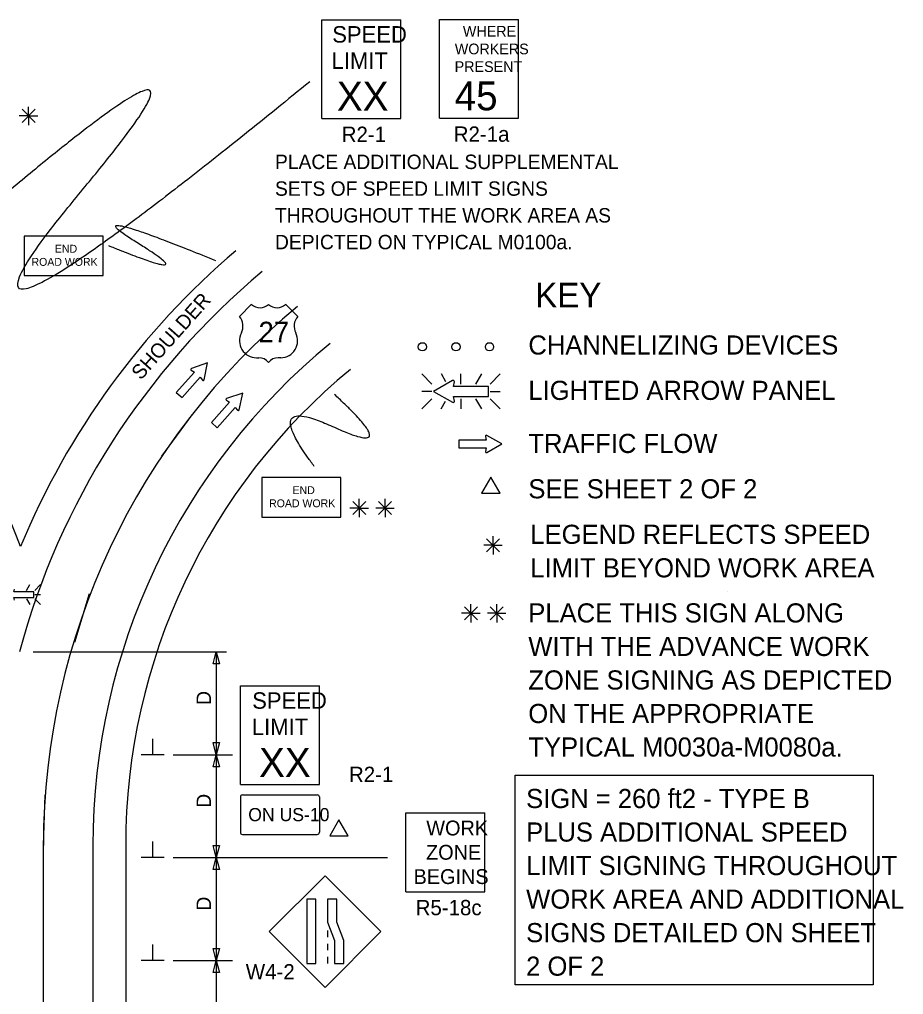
# Model space of a CAD drawing. Extents: x 16303 to 18475, y 5704 to 6974.
# Drawn here: x 17006 to 17435.6, y 6452.8 to 6926.7 of the extents above; entities that cross this region are included whole.
import ezdxf

# ---------------------------------------------------------------- set-up
doc = ezdxf.new("R2010")
doc.units = 0
for name, color, linetype in [('ALI_LEGAL_EX', 7, 'Continuous'), ('MT_SCRATCH_LEVEL_E', 7, 'Continuous'), ('PAVT_EDGE_EX', 7, 'Continuous'), ('TRAFFIC_SIGNS_PR', 7, 'Continuous'), ('TYPICAL_EX', 7, 'Continuous'), ('TYPICAL_TEXT_DIMEN_EX', 7, 'Continuous'), ('TYPICAL_TEXT_DIMEN_PR', 7, 'Continuous')]:
    doc.layers.add(name, color=color, linetype=linetype)

msp = doc.modelspace()

# ---------------------------------------------------------------- linework, layer by layer
at = {"layer": 'ALI_LEGAL_EX'}
for p, q in [((17039.84, 6647.53), (17032.85, 6623.88)), ((17017.65, 6024.8), (17017.65, 6525.15))]:
    msp.add_line(p, q, dxfattribs=at)
for points in [[(17075.14, 6714.42), (17089.89, 6734.61)], [(17017.7, 6524.8), (17017.65, 6525.15), (17018.48, 6549.78)]]:
    msp.add_lwpolyline(points, dxfattribs=at)
msp.add_arc((17357.65, 6525.15), 340, 129.5666, 180, dxfattribs=at)
at = {"layer": 'MT_SCRATCH_LEVEL_E'}
for p, q in [((17097.48, 6759.79), (17089.6, 6757.11)), ((17095.77, 6751.62), (17097.48, 6759.79)), ((17091.04, 6755.33), (17082.24, 6745.42)), ((17089.5, 6756.28), (17091.04, 6755.33)), ((17085.03, 6742.93), (17093.84, 6752.84)), ((17093.84, 6752.84), (17094.96, 6751.43)), ((17082.24, 6745.42), (17085.03, 6742.93)), ((17114.56, 6745.13), (17106.68, 6742.45)), ((17112.85, 6736.96), (17114.56, 6745.13)), ((17108.12, 6740.67), (17099.32, 6730.76)), ((17106.59, 6741.62), (17108.12, 6740.67)), ((17102.12, 6728.28), (17110.92, 6738.19)), ((17110.92, 6738.19), (17112.04, 6736.77)), ((17099.32, 6730.76), (17102.12, 6728.28)), ((17232.83, 6722.29), (17219.58, 6722.29)), ((17219.58, 6722.29), (17219.58, 6718.55)), ((17232.52, 6724.07), (17232.83, 6722.29)), ((17240.44, 6720.44), (17233.2, 6724.55)), ((17219.58, 6718.55), (17232.83, 6718.55)), ((17232.83, 6718.55), (17232.52, 6716.77)), ((17233.2, 6716.29), (17240.44, 6720.44))]:
    msp.add_line(p, q, dxfattribs=at)
for centre, start, end in [((17089.75, 6756.67), 108.8028, 238.3418), ((17095.31, 6751.73), 218.4141, 348.1511), ((17106.84, 6742.01), 108.8028, 238.3418), ((17112.4, 6737.07), 218.4141, 348.1511), ((17232.98, 6724.14), 60.4248, 189.9638), ((17232.98, 6716.7), 170.0362, 299.7731)]:
    msp.add_arc(centre, 0.463, start, end, dxfattribs=at)
at = {"layer": 'PAVT_EDGE_EX'}
for p, q in [((17041.65, 6525.15), (17041.65, 6062.71)), ((17057.65, 6525.15), (17057.65, 6062.71))]:
    msp.add_line(p, q, dxfattribs=at)
for centre, radius, start, end in [((16629.65, 6525.15), 404, 21.0961, 68.7791), ((17357.65, 6525.15), 380, 130.4392, 157.5011), ((17357.65, 6525.15), 364, 129.9322, 165.0045), ((17357.65, 6525.15), 316, 129.4107, 180), ((17357.65, 6525.15), 300, 129.4882, 180), ((17357.65, 6525.15), 300, 180, 180.00000277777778), ((17357.65, 6475.15), 300, 180, 180.00000277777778)]:
    msp.add_arc(centre, radius, start, end, dxfattribs=at)
at = {"layer": 'TRAFFIC_SIGNS_PR'}
for p, q in [((17153.01, 6926.66), (17191.41, 6926.66)), ((17153.01, 6878.66), (17153.01, 6926.66)), ((17191.41, 6878.66), (17191.41, 6926.66)), ((17210.2, 6926.75), (17248.6, 6926.75)), ((17210.2, 6878.75), (17210.2, 6926.75)), ((17248.6, 6878.75), (17248.6, 6926.75)), ((17153.01, 6878.66), (17191.41, 6878.66)), ((17210.2, 6878.75), (17248.6, 6878.75)), ((17201.51, 6754.45), (17206.44, 6749.51)), ((17213.27, 6750.63), (17211.06, 6754.45)), ((17220.59, 6749.51), (17220.59, 6754.45)), ((17227.83, 6749.51), (17230.68, 6754.45)), ((17234.74, 6749.51), (17239.68, 6754.45)), ((17206.44, 6745.96), (17201.51, 6745.96)), ((17234.74, 6745.96), (17239.68, 6745.96)), ((17201.51, 6737.47), (17206.44, 6742.4)), ((17211.02, 6737.47), (17213.13, 6741.13)), ((17220.59, 6742.4), (17220.59, 6737.47)), ((17230.72, 6737.47), (17227.87, 6742.4)), ((17234.74, 6742.4), (17239.68, 6737.47)), ((17009.51, 6649.19), (17011.14, 6652.01)), ((17013.47, 6649.19), (17016.29, 6652.02)), ((17013.47, 6647.16), (17016.29, 6647.16)), ((17011.17, 6642.31), (17009.54, 6645.13)), ((17013.47, 6645.13), (17016.29, 6642.31)), ((17113.37, 6602.81), (17151.77, 6602.81)), ((17113.37, 6554.81), (17113.37, 6602.81)), ((17151.77, 6554.81), (17151.77, 6602.81)), ((17113.37, 6554.81), (17151.77, 6554.81)), ((17113.37, 6548.81), (17113.37, 6531.61)), ((17114.37, 6549.81), (17150.77, 6549.81)), ((17151.77, 6548.81), (17151.77, 6531.61)), ((17193.74, 6502.73), (17193.74, 6541.13)), ((17193.74, 6541.13), (17232.14, 6541.13)), ((17232.14, 6502.73), (17232.14, 6541.13)), ((17114.37, 6530.61), (17150.77, 6530.61)), ((17154.51, 6510.52), (17127.36, 6483.37)), ((17181.66, 6483.37), (17154.51, 6510.52)), ((17193.74, 6502.73), (17232.14, 6502.73)), ((17127.36, 6483.37), (17154.51, 6456.21)), ((17154.51, 6456.21), (17181.66, 6483.37)), ((17155.75, 6483.86), (17155.75, 6480.66)), ((17155.75, 6477.46), (17155.75, 6474.26)), ((17155.75, 6471.06), (17155.75, 6467.86))]:
    msp.add_line(p, q, dxfattribs=at)
for points in [[(17008.25, 6802.25), (17046.65, 6802.25), (17046.65, 6821.45), (17008.25, 6821.45)], [(17123.73, 6684.89), (17162.13, 6684.89), (17162.13, 6704.09), (17123.73, 6704.09)], [(17145.61, 6499.1), (17145.61, 6467.86), (17150.11, 6467.86), (17150.11, 6499.1)], [(17155.75, 6499.1), (17155.75, 6487.92), (17159.09, 6479.04), (17159.09, 6467.86), (17163.59, 6467.86), (17163.59, 6479.04), (17160.24, 6487.92), (17160.24, 6499.1)]]:
    msp.add_lwpolyline(points, close=True, dxfattribs=at)
for points in [[(17216.52, 6751.23), (17207.23, 6745.96), (17216.52, 6740.64)], [(17217.39, 6741.27), (17216.99, 6743.53), (17234.01, 6743.53), (17234.01, 6748.34), (17216.99, 6748.34), (17217.4, 6750.62)], [(17003.55, 6644.48), (17003.32, 6645.78), (17013.05, 6645.78), (17013.05, 6648.52), (17003.32, 6648.52), (17003.56, 6649.82)]]:
    msp.add_lwpolyline(points, dxfattribs=at)
for centre in [(17201.85, 6767.64), (17218.15, 6767.64), (17234.45, 6767.64)]:
    msp.add_circle(centre, 2, dxfattribs=at)
for centre, radius, start, end in [((17216.81, 6750.71), 0.598, 350.7308, 118.8916), ((17216.81, 6741.16), 0.597, 241.4833, 9.9593), ((17114.37, 6548.81), 1, 90, 180), ((17150.77, 6548.81), 1, 0, 90), ((17114.37, 6531.61), 1, 180, 270), ((17150.77, 6531.61), 1, 270, 0)]:
    msp.add_arc(centre, radius, start, end, dxfattribs=at)
at = {"layer": 'TYPICAL_EX'}
for p, q in [((17112.93, 6782.38), (17118.83, 6788.28)), ((17141.23, 6782.38), (17135.33, 6788.28)), ((17121.17, 6762.32), (17122.35, 6762.32)), ((17132.98, 6762.32), (17131.8, 6762.32))]:
    msp.add_line(p, q, dxfattribs=at)
for centre, radius, start, end in [((17122.95, 6792.57), 5.96, 226.1404, 313.8596), ((17131.21, 6792.57), 5.96, 226.1404, 313.8596), ((17107.34, 6777.66), 7.31, 333.0977, 40.1936), ((17146.82, 6777.66), 7.31, 139.8064, 206.9023), ((17121.19, 6770.57), 8.24, 152.6698, 269.9013), ((17132.97, 6770.57), 8.24, 270.0987, 27.3302), ((17122.37, 6756.42), 5.91, 37.1038, 90.1385), ((17131.79, 6756.42), 5.91, 89.8615, 142.8962)]:
    msp.add_arc(centre, radius, start, end, dxfattribs=at)
at = {"layer": 'TYPICAL_TEXT_DIMEN_EX'}
msp.add_lwpolyline([(17246.97, 6559.43), (17420.83, 6559.43), (17420.83, 6457.5), (17246.97, 6457.5)], close=True, dxfattribs=at)
at = {"layer": 'TYPICAL_TEXT_DIMEN_PR'}
for p, q in [((17007.28, 6883.1), (17013.65, 6876.73)), ((17013.65, 6883.1), (17007.28, 6876.73)), ((17010.46, 6879.91), (17010.46, 6884.37)), ((17010.46, 6879.91), (17005.93, 6879.91)), ((17010.46, 6879.91), (17013.65, 6879.91)), ((17010.46, 6879.91), (17014.94, 6879.91)), ((17010.46, 6879.91), (17010.46, 6875.41)), ((17171.16, 6689.26), (17171.16, 6693.72)), ((17183.71, 6689.26), (17183.71, 6693.72)), ((17171.16, 6689.26), (17166.62, 6689.26)), ((17167.97, 6692.45), (17174.34, 6686.07)), ((17174.34, 6692.45), (17167.97, 6686.07)), ((17171.16, 6689.26), (17174.34, 6689.26)), ((17171.16, 6689.26), (17175.63, 6689.26)), ((17171.16, 6689.26), (17171.16, 6684.76)), ((17183.71, 6689.26), (17179.18, 6689.26)), ((17186.9, 6692.45), (17180.52, 6686.07)), ((17180.53, 6692.45), (17186.9, 6686.07)), ((17183.71, 6689.26), (17186.9, 6689.26)), ((17183.71, 6689.26), (17188.19, 6689.26)), ((17183.71, 6689.26), (17183.71, 6684.76)), ((17233.01, 6674.32), (17239.39, 6667.95)), ((17239.39, 6674.32), (17233.01, 6667.95)), ((17236.2, 6671.13), (17236.2, 6675.59)), ((17236.2, 6671.13), (17231.67, 6671.13)), ((17236.2, 6671.13), (17239.39, 6671.13)), ((17236.2, 6671.13), (17240.68, 6671.13)), ((17236.2, 6671.13), (17236.2, 6666.63)), ((17222.24, 6641.27), (17228.61, 6634.9)), ((17228.61, 6641.27), (17222.24, 6634.9)), ((17225.42, 6638.08), (17225.42, 6642.54)), ((17234.79, 6641.27), (17241.17, 6634.9)), ((17241.17, 6641.27), (17234.79, 6634.9)), ((17237.98, 6638.08), (17237.98, 6642.54)), ((17225.42, 6638.08), (17220.89, 6638.08)), ((17225.42, 6638.08), (17228.61, 6638.08)), ((17225.42, 6638.08), (17229.9, 6638.08)), ((17225.42, 6638.08), (17225.42, 6633.58)), ((17237.98, 6638.08), (17233.45, 6638.08)), ((17237.98, 6638.08), (17241.17, 6638.08)), ((17237.98, 6638.08), (17242.46, 6638.08)), ((17237.98, 6638.08), (17237.98, 6633.58)), ((17012.72, 6619.33), (17106.65, 6619.33)), ((17100.08, 6613.47), (17101.65, 6619.33)), ((17101.65, 6619.33), (17101.65, 6569.33)), ((17101.65, 6619.33), (17103.22, 6613.47)), ((17101.65, 6613.47), (17100.08, 6613.47)), ((17103.22, 6613.47), (17101.65, 6613.47)), ((17070.77, 6569.33), (17070.77, 6577.11)), ((17101.65, 6569.33), (17100.08, 6575.19)), ((17100.08, 6575.19), (17101.65, 6575.19)), ((17101.65, 6575.19), (17103.22, 6575.19)), ((17103.22, 6575.19), (17101.65, 6569.33)), ((17076.4, 6569.33), (17065.15, 6569.33)), ((17080.65, 6569.33), (17109.57, 6569.33)), ((17100.08, 6563.47), (17101.65, 6569.33)), ((17101.65, 6569.33), (17101.65, 6519.33)), ((17101.65, 6569.33), (17103.22, 6563.47)), ((17101.65, 6563.47), (17100.08, 6563.47)), ((17103.22, 6563.47), (17101.65, 6563.47)), ((17070.77, 6519.33), (17070.77, 6527.11)), ((17101.65, 6519.33), (17100.08, 6525.19)), ((17100.08, 6525.19), (17101.65, 6525.19)), ((17101.65, 6525.19), (17103.22, 6525.19)), ((17103.22, 6525.19), (17101.65, 6519.33)), ((17076.4, 6519.33), (17065.15, 6519.33)), ((17080.65, 6519.33), (17184.86, 6519.33)), ((17100.08, 6513.47), (17101.65, 6519.33)), ((17101.65, 6519.33), (17103.22, 6513.47)), ((17101.65, 6519.33), (17101.65, 6469.33)), ((17101.65, 6513.47), (17100.08, 6513.47)), ((17103.22, 6513.47), (17101.65, 6513.47)), ((17070.77, 6469.33), (17070.77, 6477.11)), ((17101.65, 6469.33), (17100.08, 6475.19)), ((17100.08, 6475.19), (17101.65, 6475.19)), ((17101.65, 6475.19), (17103.22, 6475.19)), ((17103.22, 6475.19), (17101.65, 6469.33)), ((17076.4, 6469.33), (17065.15, 6469.33)), ((17080.65, 6469.33), (17109.57, 6469.33)), ((17100.08, 6463.47), (17101.65, 6469.33)), ((17101.65, 6469.33), (17101.65, 6419.33)), ((17101.65, 6469.33), (17103.22, 6463.47)), ((17101.65, 6463.47), (17100.08, 6463.47)), ((17103.22, 6463.47), (17101.65, 6463.47))]:
    msp.add_line(p, q, dxfattribs=at)
for points in [[(17235.16, 6704.27), (17230.63, 6696.43), (17239.68, 6696.43)], [(17161.31, 6537.67), (17156.79, 6529.84), (17165.84, 6529.84)]]:
    msp.add_lwpolyline(points, close=True, dxfattribs=at)
for points in [[(17147.1, 6896.49), (16938.05, 6725.63), (17135.55, 6962.67), (16939.82, 6790.7)], [(17049.25, 6816.88), (17096.79, 6797.48), (17030.02, 6838.72), (17101.33, 6809.58)], [(17149.31, 6709.45), (17122.41, 6745.3), (17193.74, 6712.56), (17159.13, 6744.44)], [(17350.08, 6648.86), (17350.1, 6648.86), (17350.1, 6648.86), (17350.1, 6648.86)]]:
    msp.add_open_spline(points, degree=2, dxfattribs=at)

# ---------------------------------------------------------------- texts
at = {"layer": 'TRAFFIC_SIGNS_PR'}
for s, height, p in [('SPEED', 8, (17158.04, 6915.52)), ('WHERE', 5.2, (17221.51, 6918.43)), ('WORKERS', 5.2, (17217.59, 6909.83)), ('LIMIT', 8, (17157.71, 6902.72)), ('PRESENT', 5.2, (17217.52, 6901.23)), ('45', 14.031, (17217.51, 6882.6)), ('XX', 14.031, (17160.31, 6882.42)), ('R2-1', 7.44, (17162.62, 6867.22)), ('R2-1a', 7.44, (17217.06, 6867.31)), ('PLACE ADDITIONAL SUPPLEMENTAL', 7, (17130.2, 6854.05)), ('SETS OF SPEED LIMIT SIGNS', 7, (17130.2, 6841.05)), ('THROUGHOUT THE WORK AREA AS', 7, (17130.2, 6828.05)), ('DEPICTED ON TYPICAL M0100a.', 7, (17130.2, 6815.05)), ('END', 3.831, (17023.25, 6813.38)), ('ROAD WORK', 3.831, (17011.86, 6807)), ('END', 3.831, (17138.73, 6696.02)), ('ROAD WORK', 3.831, (17127.34, 6689.63)), ('PLACE THIS SIGN ALONG', 9.3, (17253.31, 6633.62)), ('WITH THE ADVANCE WORK', 9.3, (17253.31, 6617.32)), ('ZONE SIGNING AS DEPICTED', 9.3, (17253.31, 6601.02)), ('SPEED', 8, (17119.13, 6591.67)), ('ON THE APPROPRIATE', 9.3, (17253.31, 6584.72)), ('LIMIT', 8, (17118.97, 6578.87)), ('TYPICAL M0030a-M0080a.', 9.3, (17253.31, 6568.42)), ('XX', 14.031, (17122.48, 6558.57)), ('R2-1', 7.44, (17166.15, 6556.06)), ('ON US-10', 6.4, (17117.2, 6537.01)), ('WORK', 7.217, (17203.74, 6530.09)), ('ZONE', 7.217, (17203.62, 6518.28)), ('BEGINS', 7.217, (17197.55, 6506.47)), ('R5-18c', 7.44, (17198.55, 6491.29)), ('W4-2', 7.441, (17116.01, 6460.08))]:
    msp.add_text(s, height=height, dxfattribs=at).set_placement(p)
at = {"layer": 'TYPICAL_EX'}
msp.add_text('27', height=10, dxfattribs=at).set_placement((17122.19, 6769.81))
at = {"layer": 'TYPICAL_TEXT_DIMEN_EX'}
for s, height, p in [('KEY', 12, (17256.69, 6786.75)), ('CHANNELIZING DEVICES', 9.3, (17253.34, 6763.86)), ('LIGHTED ARROW PANEL', 9.3, (17253.34, 6741.81)), ('TRAFFIC FLOW', 9.3, (17253.34, 6716.01)), ('SEE SHEET 2 OF 2', 9.3, (17253.34, 6693.96)), ('LEGEND REFLECTS SPEED', 9.3, (17254.3, 6671.83)), ('LIMIT BEYOND WORK AREA', 9.3, (17254.3, 6655.53)), ('SIGN = 260 ft2 - TYPE B', 9.3, (17252.25, 6543.39)), ('PLUS ADDITIONAL SPEED', 9.3, (17252.25, 6527.09)), ('LIMIT SIGNING THROUGHOUT', 9.3, (17252.25, 6510.79)), ('WORK AREA AND ADDITIONAL', 9.3, (17252.25, 6494.49)), ('SIGNS DETAILED ON SHEET', 9.3, (17252.25, 6478.19)), ('2 OF 2', 9.3, (17252.25, 6461.89))]:
    msp.add_text(s, height=height, dxfattribs=at).set_placement(p)
at = {"layer": 'TYPICAL_TEXT_DIMEN_PR'}
for s, rotation, p in [('SHOULDER', 48.378, (17065, 6751.09)), ('D', 90, (17099.09, 6593.55)), ('D', 90, (17099.09, 6543.55)), ('D', 90, (17099.09, 6493.55))]:
    msp.add_text(s, height=7, rotation=rotation, dxfattribs=at).set_placement(p)

doc.saveas('drawing.dxf')
